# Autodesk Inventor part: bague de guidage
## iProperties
Created: 2002-06
Part Number: bague de guidage
Material: Par défaut
Document SubType Name: Modélisation
Designer: REVEST Pierre
Control State: 0
Master: False
Checked Out: False
Shininess: 69.0
Length Units: 11269
Angle Units: 11279
Time Units: 11290
Mass Units: 11283
Length Display Precision: 3
Angle Display Precision: 2
Density: 0.0
Volumn: 0.0
Area: 0.0
PropertySet Name: Model Information
Author: REVEST Pierre
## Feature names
1. Extrusion1
2. Chanfrein1 [Chamfer]
3. Perçage1 [Hole]
4. Extrusion2
5. Chanfrein2 [Chamfer]
6. Extrusion6
7. Extrusion7
8. Extrusion8
